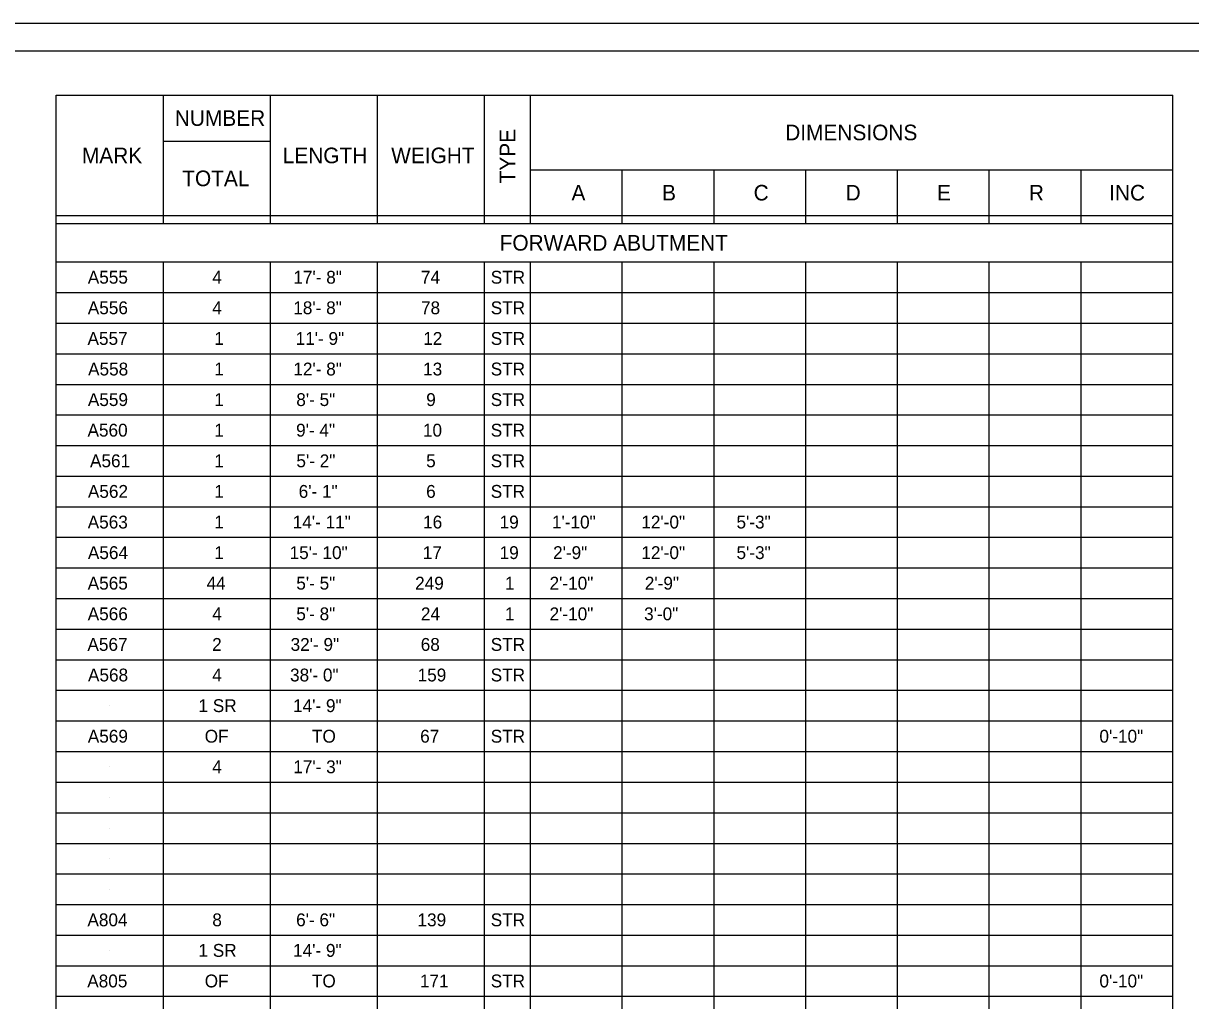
# Model space of a CAD drawing. Extents: x -9.2 to 26.7, y -24.6 to -2.6.
# Drawn here: x 7.28 to 20, y -13.46 to -2.81 of the extents above; entities that cross this region are included whole.
import ezdxf

# ---------------------------------------------------------------- set-up
doc = ezdxf.new("R2010")
doc.units = 0
for name, color, linetype in [('BR_P_Gen_Text', 7, 'Continuous'), ('SC_Scratch1', 7, 'Continuous'), ('SH_Border', 7, 'Continuous'), ('SH_Cut_Line', 7, 'Continuous'), ('TX_P_1', 7, 'Continuous')]:
    doc.layers.add(name, color=color, linetype=linetype)

msp = doc.modelspace()

# ---------------------------------------------------------------- linework, layer by layer
at = {"layer": 'BR_P_Gen_Text'}
for p, q in [((7.637, -3.594), (19.803, -3.594)), ((7.637, -21.411), (7.637, -3.594)), ((8.804, -4.994), (8.804, -3.594)), ((9.971, -4.995), (9.971, -3.594)), ((11.137, -4.995), (11.137, -3.594)), ((12.304, -4.995), (12.304, -3.594)), ((12.804, -4.995), (12.804, -3.594)), ((19.803, -21.411), (19.803, -3.594)), ((8.804, -4.094), (9.971, -4.094)), ((12.804, -4.407), (19.804, -4.407)), ((13.804, -4.995), (13.804, -4.407)), ((14.804, -4.995), (14.804, -4.407)), ((15.804, -4.995), (15.804, -4.407)), ((16.804, -4.995), (16.804, -4.407)), ((17.804, -4.994), (17.804, -4.407)), ((18.804, -4.994), (18.804, -4.407)), ((7.637, -4.907), (19.803, -4.907)), ((7.637, -4.994), (19.803, -4.994)), ((7.637, -5.411), (19.804, -5.411)), ((7.637, -5.411), (19.804, -5.411)), ((8.804, -21.078), (8.804, -5.411)), ((9.971, -21.078), (9.971, -5.411)), ((11.138, -21.411), (11.137, -5.411)), ((12.304, -21.411), (12.304, -5.411)), ((12.804, -21.078), (12.804, -5.411)), ((13.804, -21.078), (13.804, -5.411)), ((14.804, -21.078), (14.804, -5.411)), ((15.804, -21.078), (15.804, -5.411)), ((16.804, -21.078), (16.804, -5.411)), ((17.804, -21.078), (17.804, -5.411)), ((18.804, -21.078), (18.804, -5.411)), ((7.637, -5.745), (19.803, -5.745)), ((7.637, -6.078), (19.803, -6.078)), ((7.637, -6.411), (19.803, -6.411)), ((7.637, -6.745), (19.803, -6.745)), ((7.637, -7.078), (19.804, -7.078)), ((7.637, -7.411), (19.803, -7.411)), ((7.637, -7.745), (19.803, -7.744)), ((7.637, -8.078), (19.804, -8.078)), ((7.637, -8.411), (19.804, -8.411)), ((7.637, -8.745), (19.803, -8.745)), ((7.637, -9.078), (19.803, -9.078)), ((7.637, -9.411), (19.803, -9.411)), ((7.637, -9.745), (19.804, -9.745)), ((7.637, -10.078), (19.804, -10.078)), ((7.637, -10.411), (19.804, -10.411)), ((7.637, -10.745), (19.804, -10.745)), ((7.637, -11.078), (19.804, -11.078)), ((7.637, -11.411), (19.803, -11.411)), ((7.637, -11.745), (19.803, -11.745)), ((7.637, -12.078), (19.803, -12.078)), ((7.637, -12.411), (19.803, -12.411)), ((7.637, -12.744), (19.803, -12.745)), ((7.637, -13.078), (19.803, -13.078)), ((7.638, -13.411), (19.803, -13.411))]:
    msp.add_line(p, q, dxfattribs=at)
at = {"layer": 'SC_Scratch1'}
for p, q in [((13.72, -5.203), (13.72, -5.203)), ((8.221, -5.578), (8.221, -5.578)), ((8.221, -5.911), (8.221, -5.911)), ((8.221, -6.245), (8.221, -6.245)), ((8.221, -6.578), (8.221, -6.578)), ((8.221, -6.911), (8.221, -6.911)), ((8.221, -7.244), (8.221, -7.244)), ((8.221, -7.578), (8.221, -7.578)), ((8.221, -7.911), (8.221, -7.911)), ((8.221, -8.245), (8.221, -8.245)), ((8.221, -8.578), (8.221, -8.578)), ((8.221, -8.911), (8.221, -8.911)), ((8.221, -9.245), (8.221, -9.245)), ((8.221, -9.578), (8.221, -9.578)), ((8.221, -9.911), (8.221, -9.911)), ((8.221, -10.245), (8.221, -10.245)), ((8.221, -10.578), (8.221, -10.578)), ((8.221, -10.911), (8.221, -10.911)), ((8.221, -11.245), (8.221, -11.245)), ((8.221, -11.578), (8.221, -11.578)), ((8.221, -11.911), (8.221, -11.911)), ((8.221, -12.245), (8.221, -12.245)), ((8.221, -12.578), (8.221, -12.578)), ((8.221, -12.911), (8.221, -12.911)), ((8.221, -13.244), (8.221, -13.244))]:
    msp.add_line(p, q, dxfattribs=at)
at = {"layer": 'SH_Border'}
msp.add_lwpolyline([(-5.966, -3.112), (25.534, -3.112), (25.534, -24.112), (-5.966, -24.112)], close=True, dxfattribs=at)
at = {"layer": 'SH_Cut_Line'}
msp.add_lwpolyline([(26.096, -24.462), (-7.904, -24.462), (-7.904, -2.812), (26.096, -2.812)], close=True, dxfattribs=at)

# ---------------------------------------------------------------- texts
at = {"layer": 'BR_P_Gen_Text'}
for s, p in [('A555', (7.98, -5.648)), ('4', (9.336, -5.648)), (' 17\'- 8"', (10.168, -5.648)), ('74', (11.61, -5.648)), ('STR', (12.371, -5.648)), ('A556', (7.98, -5.981)), ('4', (9.336, -5.981)), (' 18\'- 8"', (10.167, -5.981)), ('78', (11.611, -5.981)), ('STR', (12.371, -5.981)), ('A557', (7.977, -6.315)), ('1', (9.358, -6.315)), (' 11\'- 9"', (10.193, -6.315)), ('12', (11.635, -6.315)), ('STR', (12.371, -6.315)), ('A558', (7.983, -6.648)), ('1', (9.358, -6.648)), (' 12\'- 8"', (10.168, -6.648)), ('13', (11.634, -6.648)), ('STR', (12.371, -6.648)), ('A559', (7.981, -6.981)), ('1', (9.358, -6.981)), (' 8\'- 5"', (10.2, -6.981)), ('9', (11.668, -6.981)), ('STR', (12.371, -6.981)), ('A560', (7.977, -7.314)), ('1', (9.358, -7.314)), (' 9\'- 4"', (10.198, -7.314)), ('10', (11.632, -7.314)), ('STR', (12.371, -7.314)), ('A561', (8.004, -7.648)), ('1', (9.358, -7.648)), (' 5\'- 2"', (10.201, -7.648)), ('5', (11.667, -7.648)), ('STR', (12.371, -7.648)), ('A562', (7.981, -7.981)), ('1', (9.358, -7.981)), (' 6\'- 1"', (10.226, -7.981)), ('6', (11.667, -7.981)), ('STR', (12.371, -7.981)), ('A563', (7.979, -8.315)), ('1', (9.358, -8.315)), (' 14\'- 11"', (10.161, -8.315)), ('16', (11.634, -8.315)), ('19', (12.468, -8.315)), ('1\'-10"', (13.038, -8.315)), ('12\'-0"', (14.012, -8.315)), ('5\'-3"', (15.049, -8.315)), ('A564', (7.981, -8.648)), ('1', (9.358, -8.648)), (' 15\'- 10"', (10.127, -8.648)), ('17', (11.631, -8.648)), ('19', (12.468, -8.648)), ('2\'-9"', (13.05, -8.648)), ('12\'-0"', (14.012, -8.648)), ('5\'-3"', (15.049, -8.648)), ('A565', (7.979, -8.981)), ('44', (9.274, -8.981)), (' 5\'- 5"', (10.2, -8.981)), ('249', (11.547, -8.981)), ('1', (12.525, -8.981)), ('2\'-10"', (13.012, -8.981)), ('2\'-9"', (14.05, -8.981)), ('A566', (7.979, -9.315)), ('4', (9.336, -9.315)), (' 5\'- 8"', (10.2, -9.315)), ('24', (11.61, -9.315)), ('1', (12.525, -9.315)), ('2\'-10"', (13.012, -9.315)), ('3\'-0"', (14.042, -9.315)), ('A567', (7.976, -9.648)), ('2', (9.335, -9.648)), (' 32\'- 9"', (10.138, -9.648)), ('68', (11.608, -9.648)), ('STR', (12.371, -9.648)), ('A568', (7.982, -9.981)), ('4', (9.336, -9.981)), (' 38\'- 0"', (10.132, -9.981)), ('159', (11.574, -9.981)), ('STR', (12.371, -9.981)), ('1 SR', (9.186, -10.315)), (' 14\'- 9"', (10.165, -10.315)), ('A569', (7.98, -10.648)), ('OF', (9.254, -10.648)), ('TO', (10.423, -10.648)), ('67', (11.602, -10.648)), ('STR', (12.371, -10.648)), ('0\'-10"', (19.004, -10.648)), ('4', (9.336, -10.981)), (' 17\'- 3"', (10.167, -10.981)), ('A804', (7.976, -12.648)), ('8', (9.337, -12.648)), (' 6\'- 6"', (10.198, -12.648)), ('139', (11.573, -12.648)), ('STR', (12.371, -12.648)), ('1 SR', (9.186, -12.981)), (' 14\'- 9"', (10.165, -12.981)), ('A805', (7.974, -13.314)), ('OF', (9.254, -13.314)), ('TO', (10.422, -13.314)), ('171', (11.599, -13.314)), ('STR', (12.371, -13.314)), ('0\'-10"', (19.004, -13.314))]:
    msp.add_text(s, height=0.14, dxfattribs=at).set_placement(p)
at = {"layer": 'TX_P_1'}
for s, rotation, p in [('NUMBER', 0.0002, (8.928, -3.929)), ('DIMENSIONS', 0.0002, (15.58, -4.086)), ('TYPE', 90.0002, (12.639, -4.556)), ('MARK', 0.0002, (7.916, -4.336)), ('LENGTH', 0.0002, (10.104, -4.336)), ('WEIGHT', 0.0002, (11.286, -4.336)), ('TOTAL', 0.0002, (9.009, -4.586)), ('A', 0.0002, (13.251, -4.742)), ('B', 0.0002, (14.238, -4.742)), ('C', 0.0002, (15.236, -4.742)), ('D', 0.0002, (16.238, -4.742)), ('E', 0.0002, (17.235, -4.742)), ('R', 0.0002, (18.235, -4.742)), ('INC', 0.0002, (19.11, -4.742)), ('FORWARD ABUTMENT', 0.0002, (12.468, -5.288))]:
    msp.add_text(s, height=0.17, rotation=rotation, dxfattribs=at).set_placement(p)

doc.saveas('drawing.dxf')
